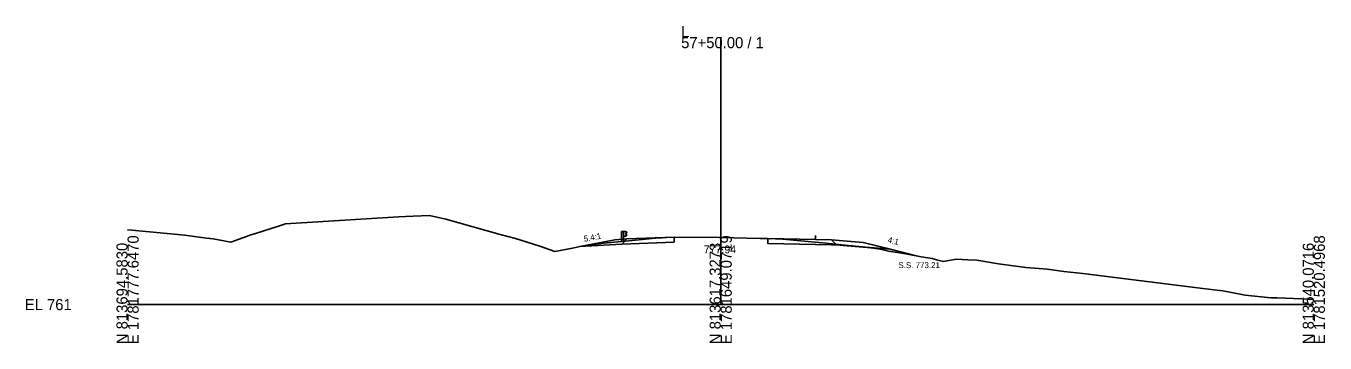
# Model space of a CAD drawing. Extents: x -26 to 7903, y -10 to 9573.
# Drawn here: x 1974.3 to 2302.8, y 8490.3 to 8570.3 of the extents above; entities that cross this region are included whole.
import ezdxf

# ---------------------------------------------------------------- set-up
doc = ezdxf.new("R2010")
doc.units = 0
for name, color, linetype in [('Exist Cross Section Cell', 7, 'Continuous'), ('Exist XS Center Line Elevation Label', 7, 'Continuous'), ('Exist XS Ground Line', 7, 'Continuous'), ('Prop XS Ditch Slope Text', 7, 'Continuous'), ('Prop XS Dump Level', 7, 'Continuous'), ('Prop XS Earthwork Shape', 7, 'Continuous'), ('Prop XS EOT Tick Mark', 7, 'Continuous'), ('Prop XS Finish Grade', 7, 'Continuous'), ('Prop XS Finish Grade Earthwork', 7, 'Continuous'), ('Prop XS Finish Grade Paved Shoulder', 7, 'Continuous'), ('Prop XS Finish Grade Pavement', 7, 'Continuous'), ('Prop XS Guardrail', 7, 'Continuous'), ('Prop XS Hydro Fill Slope Data', 7, 'Continuous'), ('Prop XS Pvmt Edge Slope', 7, 'Continuous'), ('Prop XS Side Slope Text', 7, 'Continuous'), ('Prop XS SS Elevation Text', 7, 'Continuous'), ('Prop XS Subgrade Earthwork', 7, 'Continuous'), ('Scratch_Level_3', 7, 'Continuous'), ('Scratch_Level_6', 7, 'Continuous')]:
    doc.layers.add(name, color=color, linetype=linetype)

msp = doc.modelspace()

# ---------------------------------------------------------------- linework, layer by layer
at = {"layer": 'Exist Cross Section Cell'}
for p, q in [((2150, 8500), (2150, 8567.54)), ((2000, 8500), (2150, 8500)), ((2150, 8500), (2300, 8500))]:
    msp.add_line(p, q, dxfattribs=at)
at = {"layer": 'Exist XS Ground Line'}
for p, q in [((2039.98, 8520.4), (2068.49, 8522.15)), ((2068.49, 8522.15), (2072.24, 8522.3)), ((2072.24, 8522.3), (2076.39, 8522.51)), ((2076.39, 8522.51), (2080.46, 8521.56)), ((2032.39, 8517.92), (2038.14, 8519.83)), ((2038.14, 8519.83), (2039.98, 8520.4)), ((2080.46, 8521.56), (2094.23, 8517.73)), ((2000, 8518.85), (2001.1, 8518.8)), ((2001.1, 8518.8), (2014.44, 8517.5)), ((2014.44, 8517.5), (2019.97, 8516.79)), ((2019.97, 8516.79), (2021.66, 8516.58)), ((2021.66, 8516.58), (2023.03, 8516.37)), ((2023.03, 8516.37), (2026.15, 8515.72)), ((2026.15, 8515.72), (2030.09, 8517.19)), ((2030.09, 8517.19), (2030.96, 8517.53)), ((2030.96, 8517.53), (2032.39, 8517.92)), ((2094.23, 8517.73), (2098.08, 8516.68)), ((2098.08, 8516.68), (2099.42, 8516.27)), ((2099.42, 8516.27), (2104.28, 8514.76)), ((2120.36, 8515.53), (2126.74, 8516.07)), ((2126.74, 8516.07), (2133.5, 8516.73)), ((2133.5, 8516.73), (2135.2, 8516.89)), ((2135.2, 8516.89), (2136.26, 8516.95)), ((2136.26, 8516.95), (2138.26, 8517.05)), ((2138.26, 8517.05), (2149.65, 8516.95)), ((2149.65, 8516.95), (2150, 8516.94)), ((2150, 8516.94), (2159.96, 8516.72)), ((2159.96, 8516.72), (2161.92, 8516.68)), ((2161.92, 8516.68), (2165.73, 8516.48)), ((2165.73, 8516.48), (2169.34, 8516.15)), ((2169.34, 8516.15), (2176.7, 8515.48)), ((2104.28, 8514.76), (2108.04, 8513.38)), ((2108.04, 8513.38), (2112.49, 8514.26)), ((2112.49, 8514.26), (2114.35, 8514.68)), ((2114.35, 8514.68), (2117.92, 8515.2)), ((2117.92, 8515.2), (2120.36, 8515.53)), ((2176.7, 8515.48), (2180.68, 8515.12)), ((2180.68, 8515.12), (2181.45, 8515.02)), ((2181.45, 8515.02), (2188.63, 8514.24)), ((2188.63, 8514.24), (2190.72, 8513.9)), ((2190.72, 8513.9), (2192.47, 8513.51)), ((2192.47, 8513.51), (2195.35, 8513.03)), ((2195.35, 8513.03), (2198.56, 8512.45)), ((2198.56, 8512.45), (2200.74, 8512.07)), ((2200.74, 8512.07), (2203.49, 8511.61)), ((2203.49, 8511.61), (2204.59, 8511.34)), ((2204.59, 8511.34), (2206.38, 8510.87)), ((2206.38, 8510.87), (2207.71, 8511.12)), ((2207.71, 8511.12), (2209.63, 8511.49)), ((2209.63, 8511.49), (2212.48, 8511.3)), ((2212.48, 8511.3), (2214.75, 8511.23)), ((2214.75, 8511.23), (2220.28, 8510.3)), ((2220.28, 8510.3), (2227.2, 8509.35)), ((2227.2, 8509.35), (2232.65, 8508.93)), ((2232.65, 8508.93), (2236.78, 8508.39)), ((2236.78, 8508.39), (2241.59, 8507.81)), ((2241.59, 8507.81), (2271.94, 8504.09)), ((2271.94, 8504.09), (2276.2, 8503.55)), ((2276.2, 8503.55), (2277, 8503.46)), ((2277, 8503.46), (2282.68, 8502.34)), ((2282.68, 8502.34), (2289.14, 8501.69)), ((2289.14, 8501.69), (2290.69, 8501.74)), ((2290.69, 8501.74), (2297, 8501.44)), ((2297, 8501.44), (2300, 8501.25))]:
    msp.add_line(p, q, dxfattribs=at)
at = {"layer": 'Prop XS Dump Level'}
for p, q in [((2161.9, 8516.7), (2174, 8516.46)), ((2174, 8516.46), (2161.9, 8516.7))]:
    msp.add_line(p, q, dxfattribs=at)
at = {"layer": 'Prop XS Earthwork Shape'}
for points in [[(2138.26, 8515.8), (2124.96, 8515.27), (2114.35, 8514.68), (2117.92, 8515.2), (2120.36, 8515.53), (2126.74, 8516.07), (2133.5, 8516.73), (2135.2, 8516.89), (2136.26, 8516.95), (2138.26, 8517.05)], [(2186, 8514.51), (2186.68, 8514.46), (2181.45, 8515.02), (2180.68, 8515.12), (2176.7, 8515.48), (2169.34, 8516.15), (2165.73, 8516.48), (2161.92, 8516.68), (2161.92, 8515.43), (2174, 8515.16), (2178, 8515.08), (2179.28, 8515.05), (2181, 8514.91)], [(2186.68, 8514.46), (2188.63, 8514.24), (2190.72, 8513.9), (2192.47, 8513.51), (2195.35, 8513.03), (2198.56, 8512.45), (2199.89, 8512.21), (2192.92, 8513.96)]]:
    msp.add_lwpolyline(points, close=True, dxfattribs=at)
at = {"layer": 'Prop XS EOT Tick Mark'}
msp.add_line((2174, 8516.41), (2174, 8517.41), dxfattribs=at)
at = {"layer": 'Prop XS Finish Grade'}
for p, q in [((2123.26, 8516.33), (2114.35, 8514.68)), ((2126.26, 8516.57), (2123.26, 8516.33)), ((2178, 8516.33), (2181, 8516.09)), ((2181, 8516.09), (2186, 8515.69)), ((2186, 8515.69), (2192.92, 8513.96))]:
    msp.add_line(p, q, dxfattribs=at)
at = {"layer": 'Prop XS Finish Grade Earthwork'}
msp.add_line((2192.92, 8513.96), (2199.89, 8512.21), dxfattribs=at)
at = {"layer": 'Prop XS Finish Grade Paved Shoulder'}
msp.add_line((2174, 8516.41), (2178, 8516.33), dxfattribs=at)
at = {"layer": 'Prop XS Finish Grade Pavement'}
for p, q in [((2138.26, 8517.05), (2126.26, 8516.57)), ((2161.92, 8516.68), (2174, 8516.41))]:
    msp.add_line(p, q, dxfattribs=at)
at = {"layer": 'Prop XS Guardrail'}
for p, q in [((2124.94, 8518.45), (2125.44, 8518.45)), ((2124.94, 8515.95), (2124.94, 8518.45)), ((2125.44, 8518.45), (2125.94, 8518.45)), ((2125.44, 8518.45), (2125.44, 8515.95)), ((2125.94, 8517.31), (2125.44, 8517.31)), ((2125.94, 8518.45), (2126.23, 8518.25)), ((2126.23, 8518.13), (2125.94, 8517.93)), ((2125.94, 8517.93), (2125.94, 8517.83)), ((2125.94, 8517.83), (2126.23, 8517.63)), ((2126.23, 8517.51), (2125.94, 8517.31)), ((2126.23, 8518.25), (2126.26, 8518.19)), ((2126.26, 8518.19), (2126.23, 8518.13)), ((2126.23, 8517.63), (2126.26, 8517.57)), ((2126.26, 8517.57), (2126.23, 8517.51))]:
    msp.add_line(p, q, dxfattribs=at)
at = {"layer": 'Prop XS Hydro Fill Slope Data'}
msp.add_line((2186, 8515.69), (2199.89, 8512.21), dxfattribs=at)
at = {"layer": 'Prop XS Pvmt Edge Slope'}
for p, q in [((2126.26, 8516.57), (2124.96, 8515.27)), ((2178, 8516.33), (2179.28, 8515.05))]:
    msp.add_line(p, q, dxfattribs=at)
at = {"layer": 'Prop XS Subgrade Earthwork'}
for p, q in [((2138.26, 8515.8), (2124.96, 8515.27)), ((2138.26, 8515.8), (2138.26, 8517.05)), ((2161.92, 8515.43), (2161.92, 8516.68)), ((2124.96, 8515.27), (2114.35, 8514.68)), ((2161.92, 8515.43), (2174, 8515.16)), ((2174, 8515.16), (2178, 8515.08)), ((2178, 8515.08), (2179.28, 8515.05)), ((2179.28, 8515.05), (2181, 8514.91)), ((2181, 8514.91), (2186, 8514.51)), ((2186, 8514.51), (2192.92, 8513.96))]:
    msp.add_line(p, q, dxfattribs=at)
at = {"layer": 'Scratch_Level_3'}
for p, q in [((2123.26, 8516.33), (2114.35, 8514.68)), ((2126.26, 8516.57), (2123.26, 8516.33)), ((2124.96, 8515.27), (2126.26, 8516.57)), ((2181, 8516.09), (2178, 8516.33)), ((2178, 8516.33), (2179.28, 8515.05)), ((2186, 8515.69), (2181, 8516.09)), ((2192.92, 8513.96), (2186, 8515.69)), ((2114.35, 8514.68), (2124.96, 8515.27)), ((2179.28, 8515.05), (2181, 8514.91)), ((2181, 8514.91), (2186, 8514.51)), ((2186, 8514.51), (2192.92, 8513.96))]:
    msp.add_line(p, q, dxfattribs=at)
at = {"layer": 'Scratch_Level_6'}
for points in [[(2138.26, 8515.8), (2138.26, 8517.05), (2136.26, 8516.95), (2135.2, 8516.89), (2133.5, 8516.73), (2126.74, 8516.07), (2120.36, 8515.53), (2117.92, 8515.2), (2114.35, 8514.68), (2124.96, 8515.27)], [(2186, 8514.51), (2186.68, 8514.46), (2181.45, 8515.02), (2180.68, 8515.12), (2176.7, 8515.48), (2169.34, 8516.15), (2165.73, 8516.48), (2161.92, 8516.68), (2161.92, 8515.43), (2174, 8515.16), (2178, 8515.08), (2179.28, 8515.05), (2181, 8514.91)]]:
    msp.add_lwpolyline(points, close=True, dxfattribs=at)

# ---------------------------------------------------------------- texts
at = {"layer": 'Exist Cross Section Cell'}
for s, p in [('L', (2140, 8567.54)), ('57+50.00 / 1', (2140, 8564.74)), ('EL 761', (1974, 8498.6))]:
    msp.add_text(s, height=2.8, dxfattribs=at).set_placement(p)
for s, p in [('E 1781777.6470', (2002.8, 8490)), ('E 1781649.0719', (2152.8, 8490)), ('E 1781520.4968', (2302.8, 8490)), ('N 813694.5830', (2000, 8490)), ('N 813617.3273', (2150, 8490)), ('N 813540.0716', (2300, 8490))]:
    msp.add_text(s, height=2.8, rotation=90, dxfattribs=at).set_placement(p)
at = {"layer": 'Exist XS Center Line Elevation Label'}
msp.add_text('777.94', height=2, dxfattribs=at).set_placement((2145.72, 8512.94))
at = {"layer": 'Prop XS Ditch Slope Text'}
msp.add_text('5.4:1', height=1.5, rotation=10.1372, dxfattribs=at).set_placement((2115.49, 8515.85))
at = {"layer": 'Prop XS Dump Level'}
for s, height, p in [('Eop', 0.3, (2161.92, 8516.38)), ('Case4', 0.04, (2186, 8515.65))]:
    msp.add_text(s, height=height, dxfattribs=at).set_placement(p)
at = {"layer": 'Prop XS Side Slope Text'}
msp.add_text('4:1', height=1.5, rotation=345.9638, dxfattribs=at).set_placement((2192.13, 8515.7))
at = {"layer": 'Prop XS SS Elevation Text'}
msp.add_text('S.S. 773.21', height=1.5, dxfattribs=at).set_placement((2194.96, 8509.21))

doc.saveas('drawing.dxf')
